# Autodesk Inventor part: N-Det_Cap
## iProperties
Shininess: 64.0
Length Units: 11272
Angle Units: 11279
Time Units: 11290
Mass Units: 11286
Length Display Precision: 3
Angle Display Precision: 2
Compacted: True
Part Number: N-Det_Cap
Document SubType Name: Modeling
Created: 2005-05
Designer: John Blackburn
Material: Aluminum-6061
Manufacturer: Standard
Standards Organization: Custom
Density: 0.0
Volumn: 0.0
Area: 0.0
PropertySet Name: Model Information
Control State: 0
Master: False
Checked Out: False
Author: John Blackburn
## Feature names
1. Extrusion1
2. Hole1
3. Hole2
